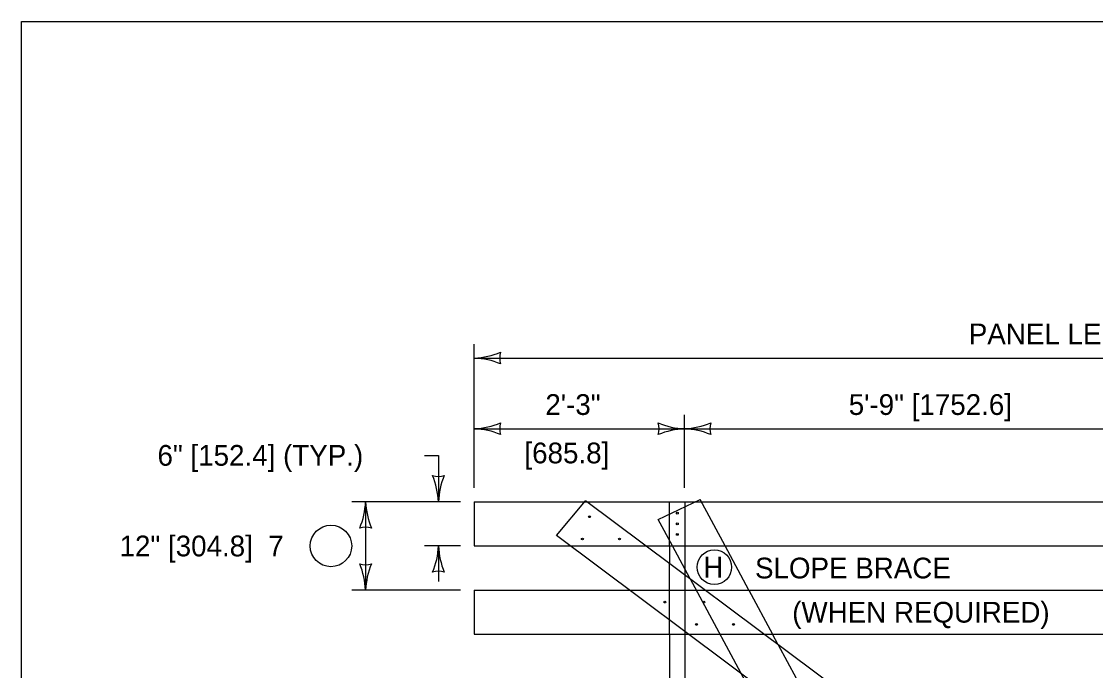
# Model space of a CAD drawing. Extents: x 49991.4 to 50021, y 49987.6 to 50011.4.
# Drawn here: x 49999.384 to 50002.489, y 49997.122 to 49998.999 of the extents above; entities that cross this region are included whole.
import ezdxf

# ---------------------------------------------------------------- set-up
doc = ezdxf.new("R2010")
doc.units = 0
for name, color, linetype in [('Level 1', 7, 'Continuous'), ('Level 2', 7, 'Continuous'), ('Level 3', 7, 'Continuous'), ('Level 4', 7, 'Continuous')]:
    doc.layers.add(name, color=color, linetype=linetype)

msp = doc.modelspace()

# ---------------------------------------------------------------- linework, layer by layer
at = {"layer": 'Level 1'}
for p, q in [((50000.6929, 49997.6101), (50000.6929, 49997.4824)), ((50000.6929, 49997.6101), (50005.041, 49997.6101)), ((50000.9301, 49997.5128), (50001.0146, 49997.6127)), ((50004.8448, 49994.752), (50001.0146, 49997.6127)), ((50004.7604, 49994.652), (50000.9301, 49997.5128)), ((50000.6929, 49997.4824), (50000.9709, 49997.4824)), ((50001.1893, 49997.4824), (50005.041, 49997.4824)), ((50001.2572, 49997.4824), (50001.2572, 49997.4315)), ((50001.317, 49997.3869), (50001.2656, 49997.4824)), ((50001.3024, 49997.3977), (50001.3024, 49997.4824)), ((50001.4868, 49997.3546), (50001.418, 49997.4824)), ((50000.6929, 49997.3546), (50000.6929, 49997.2268)), ((50000.6929, 49997.3546), (50001.142, 49997.3546)), ((50001.3604, 49997.3546), (50005.041, 49997.3546)), ((50000.6929, 49997.2268), (50001.3131, 49997.2268)), ((50001.2572, 49997.2268), (50001.2572, 49997.099)), ((50001.3024, 49997.099), (50001.3024, 49997.2268)), ((50001.5315, 49997.2268), (50005.041, 49997.2268)), ((50001.5715, 49997.1969), (50001.5554, 49997.2268))]:
    msp.add_line(p, q, dxfattribs=at)
msp.add_lwpolyline([(49999.3835, 49998.9992), (50016.7501, 49998.9992), (50016.7501, 49987.7988), (49999.3835, 49987.7988)], close=True, dxfattribs=at)
for centre in [(50001.0263, 49997.5669), (50001.2799, 49997.5771), (50001.2799, 49997.5465), (50001.0053, 49997.5025), (50001.1124, 49997.5025), (50001.2799, 49997.5158), (50001.2441, 49997.3201), (50001.3562, 49997.3201), (50001.3352, 49997.2556), (50001.4423, 49997.2556)]:
    msp.add_ellipse(centre, major_axis=(0.00285, 0), ratio=0.940299, dxfattribs=at)
at = {"layer": 'Level 2'}
for centre, radius in [((50000.2784, 49997.4824), 0.06), ((50001.387, 49997.421), 0.05)]:
    msp.add_circle(centre, radius, dxfattribs=at)
at = {"layer": 'Level 3'}
for p, q in [((50000.6929, 49997.6501), (50000.6929, 49998.0656)), ((50000.6929, 49998.0256), (50005.041, 49998.0256)), ((50001.3006, 49997.6501), (50001.3006, 49997.8613)), ((50000.6929, 49997.8213), (50001.3006, 49997.8213)), ((50001.3006, 49997.8213), (50002.8632, 49997.8213)), ((50000.5492, 49997.7444), (50000.5892, 49997.7444)), ((50000.5892, 49997.7444), (50000.5892, 49997.6101)), ((50000.6529, 49997.6101), (50000.3384, 49997.6101)), ((50000.3784, 49997.6102), (50000.3784, 49997.3547)), ((50000.6529, 49997.4824), (50000.5492, 49997.4824)), ((50000.5892, 49997.4824), (50000.5892, 49997.38)), ((50000.6529, 49997.3546), (50000.3384, 49997.3546))]:
    msp.add_line(p, q, dxfattribs=at)
for centre, radius, start, end in [((50000.6814, 49998.2583), 0.233, 272.8273, 292.0772), ((50000.6837, 49997.8035), 0.2223, 67.456, 87.6395), ((50000.8211, 49998.0256), 0.0548, 162.1388, 197.8612), ((50000.6814, 49998.054), 0.233, 272.8273, 292.0772), ((50000.8211, 49997.8213), 0.0548, 162.1388, 197.8612), ((50001.3098, 49998.0434), 0.2223, 247.456, 267.6395), ((50001.1724, 49997.8213), 0.0548, 342.1388, 17.8612), ((50001.2891, 49998.054), 0.233, 272.8273, 292.0772), ((50001.4288, 49997.8213), 0.0548, 162.1388, 197.8612), ((50000.6837, 49997.5992), 0.2223, 67.456, 87.6395), ((50001.3121, 49997.5886), 0.233, 92.8273, 112.0772), ((50001.2914, 49997.5992), 0.2223, 67.456, 87.6395), ((50000.5892, 49997.7383), 0.0548, 252.1388, 287.8612), ((50000.3564, 49997.5986), 0.233, 2.8273, 22.0772), ((50000.8113, 49997.6009), 0.2223, 157.456, 177.6395), ((50000.1563, 49997.6193), 0.2223, 337.456, 357.6395), ((50000.6111, 49997.6217), 0.233, 182.8273, 202.0772), ((50000.3784, 49997.482), 0.0548, 72.1388, 107.8612), ((50000.367, 49997.4916), 0.2223, 337.456, 357.6395), ((50000.8219, 49997.4939), 0.233, 182.8273, 202.0772), ((50000.3784, 49997.4829), 0.0548, 252.1388, 287.8612), ((50000.1457, 49997.3432), 0.233, 2.8273, 22.0772), ((50000.6006, 49997.3455), 0.2223, 157.456, 177.6395), ((50000.5892, 49997.3542), 0.0548, 72.1388, 107.8612)]:
    msp.add_arc(centre, radius, start, end, dxfattribs=at)
at = {"layer": 'Level 4'}
for p, q in [((50001.2244, 49997.559), (50001.3457, 49997.6168)), ((50001.418, 49997.4824), (50001.3457, 49997.6168)), ((50001.2572, 49997.4824), (50001.2572, 49997.6101)), ((50001.3024, 49997.4824), (50001.3024, 49997.6101)), ((50001.2656, 49997.4824), (50001.2244, 49997.559)), ((50000.9709, 49997.4824), (50001.1893, 49997.4824)), ((50001.2572, 49997.2268), (50001.2572, 49997.4315)), ((50001.3024, 49997.2268), (50001.3024, 49997.3977)), ((50001.3169, 49997.3871), (50001.5412, 49996.97)), ((50001.142, 49997.3546), (50001.3604, 49997.3546)), ((50001.4868, 49997.3546), (50001.5554, 49997.2268)), ((50001.3131, 49997.2268), (50001.5315, 49997.2268)), ((50001.5715, 49997.1969), (50001.7182, 49996.9241))]:
    msp.add_line(p, q, dxfattribs=at)

# ---------------------------------------------------------------- texts
at = {"layer": 'Level 2'}
for s, p in [('PANEL LENGTH = 16\'-0" [4876.8]', (50002.1227, 49998.0656)), ('5\'-9" [1752.6]', (50001.7755, 49997.8613)), ('2\'-3"', (50000.8983, 49997.8613)), ('6" [152.4] (TYP.)', (49999.7768, 49997.7144)), ('[685.8]', (50000.8378, 49997.7213)), ('12" [304.8]  7', (49999.6671, 49997.4523)), ('H', (50001.355, 49997.391)), ('SLOPE BRACE ', (50001.5045, 49997.3885)), ('(WHEN REQUIRED)', (50001.6121, 49997.2607))]:
    msp.add_text(s, height=0.06, dxfattribs=at).set_placement(p)

doc.saveas('drawing.dxf')
